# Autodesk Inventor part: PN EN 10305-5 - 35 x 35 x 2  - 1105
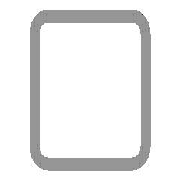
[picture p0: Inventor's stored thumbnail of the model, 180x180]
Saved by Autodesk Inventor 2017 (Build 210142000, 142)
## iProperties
Created: 2016-02
Part Number: PN EN 10305-5 - 35 x 35 x 2  - 1105
Material: Stal, miękka
Description: Rury stalowe do zastosowań precyzyjnych -  (Część 5: Rury kwadratowe, spawane, wymiarowane na zimno)
Document SubType Name: Modeling
Standard: PN
Designer: X
Standards Organization: PN
Language: pl-PL
Size Designation: 35 x 35 x 2
Categories: <MemberInstance><Categories><Category DisplayName="Kształtowniki konstrukcyjne" InternalName="089c4875-fa83-4c05-b084-43b9cc11f5ed" Mnemonic="GRDR"><CategoryPar
Stock Number: 35 x 35 x 2
Density: 7.85 g/cm^3
Appearance: Częściowo polerowana
IsCustomPart: 1
_CCFamilyMember: 22
_CCFamilyDisplayName: PN EN 10305-5 (Rury kwadratowe, spawane, wymiarowane na zimno) - Rury stalowe do zastosowań precyzyjnych -  (Część 5: Rury kwadratowe, spawane, wymiarowane na z
_FrameMemberDoc: Frame Member File
_Version: 15.0.0
_GetPNFromCC: 1
Author: X
G_L: 1105,000 mm
G_W: 35,000 mm
G_H: 35,000 mm
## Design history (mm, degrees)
node "Płaszczyzna początkowa"
node "Płaszczyzna końcowa"
sketch "Szkic"
  geometry: L1 (-17.5, -14.5)-(-17.5, 14.5); L2 (-14.5, 17.5)-(14.5, 17.5); L3 (17.5, 14.5)-(17.5, -14.5); L4 (14.5, -17.5)-(-14.5, -17.5); L5 (-14.5, 15.5)-(14.5, 15.5); L6 (15.5, 14.5)-(15.5, -14.5); L7 (14.5, -15.5)-(-14.5, -15.5); L8 (-15.5, -14.5)-(-15.5, 14.5); L9 (0, 25.37)-(0, -25.37) reference; L10 (-25.37, 0)-(25.37, 0) reference; A1 r 3 centre (-14.5, -14.5) between (-17.5, -14.5) and (-14.5, -17.5); A2 r 3 centre (-14.5, 14.5) between (-14.5, 17.5) and (-17.5, 14.5); A3 r 3 centre (14.5, 14.5) between (17.5, 14.5) and (14.5, 17.5); A4 r 3 centre (14.5, -14.5) between (14.5, -17.5) and (17.5, -14.5); A5 r 1 centre (-14.5, 14.5) between (-14.5, 15.5) and (-15.5, 14.5); A6 r 1 centre (14.5, 14.5) between (15.5, 14.5) and (14.5, 15.5); A7 r 1 centre (14.5, -14.5) between (14.5, -15.5) and (15.5, -14.5); A8 r 1 centre (-14.5, -14.5) between (-15.5, -14.5) and (-14.5, -15.5)
  constraints: 16 end point, 16 point on circle, 8 centre point, 8 tangent, 4 parallel, 3 equal radius, 2 perpendicular, 7 other
  dimensions: "d7" = 3 radius of A1 (= G_IR); "d10" = 35 distance between parallel lines of L2 L4 (= G_H); "d11" = 35 distance between parallel lines of L1 L3 (= G_W); "d12" = 2 distance between parallel lines of L3 L6 (= G_T); "d15" = 17.5 distance between parallel lines of L2 L10 (= 0.5 x d10); "d16" = 17.5 distance between parallel lines of L9 L3 (= 0.5 x d11)
extrude "Bryła" new body sketch "Szkic" stored distance "d3" = 1105 (= G_L); taper "d4" = 0 deg
node "Driven Length"
  sketch "Sketch3"
    geometry: L1 (0, 0)-(10, 0) reference
    constraints: 2 end point, 1 horizontal
  workplane "Work Plane3"
  sketch "Sketch4"
    geometry: L1 (-2, 0)-(12, 0) reference; L2 (-2, 1105)-(12, 1105) reference
    dimensions: "d18" = 1105 distance between parallel lines of L1 L2 (derived)
body "Solid1"
other parameters: "G_W" = 35 [user parameter; used in 1 equation term], "G_H" = 35 [user parameter; used in 1 equation term], "G_T" = 2 [user parameter; used in 1 equation term], "G_IR" = 3 [user parameter; used in 1 equation term], "G_L" = 1105 (= d18) [user parameter; used in 1 equation term], "G_OFFSET_START" = 0 [user parameter; used in 1 equation term], "G_OFFSET_END" = -35 [user parameter; used in 1 equation term], "d13" = 0 (computed from G_OFFSET_START), "d14" = 1105 (= G_OFFSET_END + B_L), "d17" = 90 deg
